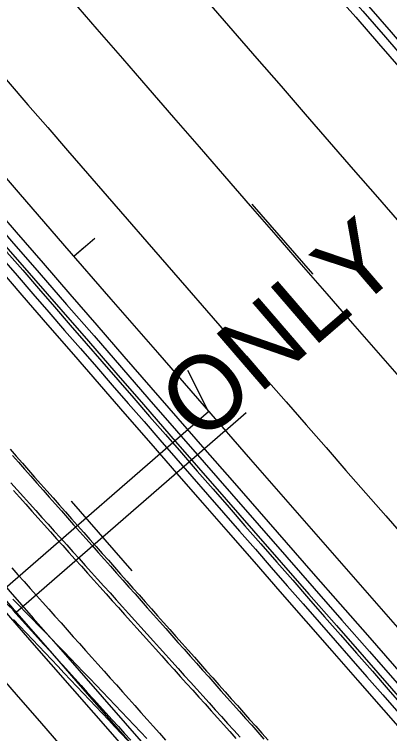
# Model space of a CAD drawing. Extents: x 2252205 to 2259955, y 13788514 to 13798103.
# Drawn here: x 2256454 to 2256494.6, y 13792111.5 to 13792189.4 of the extents above; entities that cross this region are included whole.
import ezdxf

# ---------------------------------------------------------------- set-up
doc = ezdxf.new("R2010")
doc.units = 0
for name, color, linetype in [('D_RDWY_TRACK_BUS', 7, 'Continuous'), ('D_RDWY_TRACK_TRUCK_KLEIN_CITY', 7, 'Continuous'), ('D_RDWY_TRACK_TRUCK_WB62', 7, 'Continuous'), ('GEOM_CENTERLINE_ALIGN', 7, 'Continuous'), ('GEOM_CENTERLINE_STA_100', 7, 'Continuous'), ('GEOM_CENTERLINE_STA_50', 7, 'Continuous'), ('ROAD_BIKE_SHARED_USE', 7, 'Continuous'), ('Road_Curb_Back', 7, 'Continuous'), ('Road_Curb_Face', 7, 'Continuous'), ('Road_EdgeOfPavementInside', 7, 'Continuous'), ('Road_EdgeOfPavementOutside', 7, 'Continuous'), ('ROAD_ROW_EXIST', 7, 'Continuous'), ('ROAD_ROW_PROPOSED', 7, 'Continuous'), ('ROAD_SCRATCH_DRIVE_CL', 7, 'Continuous'), ('ROAD_SCRATCH_PROP_KLEIN_LANES', 7, 'Continuous'), ('Road_Sidewalk_Back', 7, 'Continuous'), ('TRAF_PAVMRK_W_4IN_BRK', 7, 'Continuous'), ('TRAF_PAVMRK_W_4IN_SLD', 7, 'Continuous'), ('TRAF_PAVMRK_W_8IN_SLD', 7, 'Continuous'), ('TRAF_PAVMRK_W_LT_TRN_ARROW_WORD', 7, 'Continuous'), ('TRAF_PAVMRK_Y_4IN_SLD', 7, 'Continuous')]:
    doc.layers.add(name, color=color, linetype=linetype)

msp = doc.modelspace()

# ---------------------------------------------------------------- linework, layer by layer
at = {"layer": 'D_RDWY_TRACK_BUS'}
for points in [[(2256453.888, 13792137.831), (2256454.557, 13792137.083), (2256455.225, 13792136.335), (2256455.893, 13792135.587), (2256456.562, 13792134.839), (2256457.23, 13792134.091), (2256457.899, 13792133.344), (2256458.568, 13792132.597), (2256459.236, 13792131.85), (2256459.905, 13792131.103), (2256460.573, 13792130.356), (2256461.242, 13792129.61), (2256461.911, 13792128.863), (2256462.58, 13792128.117), (2256463.248, 13792127.371), (2256463.917, 13792126.624), (2256464.586, 13792125.879), (2256465.255, 13792125.133), (2256465.924, 13792124.387), (2256466.593, 13792123.641), (2256467.261, 13792122.896), (2256467.93, 13792122.15), (2256468.599, 13792121.405), (2256469.268, 13792120.66), (2256469.937, 13792119.915), (2256470.606, 13792119.17), (2256471.275, 13792118.425), (2256471.944, 13792117.68), (2256472.613, 13792116.935), (2256473.283, 13792116.19), (2256473.952, 13792115.446), (2256474.621, 13792114.701), (2256475.29, 13792113.957), (2256475.959, 13792113.212), (2256476.628, 13792112.468), (2256477.297, 13792111.723), (2256477.966, 13792110.979)], [(2256453.83, 13792124.845), (2256454.503, 13792124.106), (2256455.175, 13792123.366), (2256455.847, 13792122.626), (2256456.518, 13792121.887), (2256457.19, 13792121.147), (2256457.862, 13792120.407), (2256458.534, 13792119.666), (2256459.205, 13792118.926), (2256459.877, 13792118.186), (2256460.548, 13792117.445), (2256461.219, 13792116.705), (2256461.89, 13792115.964), (2256462.562, 13792115.223), (2256463.233, 13792114.483), (2256463.904, 13792113.742), (2256464.575, 13792113.001), (2256465.246, 13792112.26), (2256465.917, 13792111.519), (2256466.588, 13792110.778)]]:
    msp.add_lwpolyline(points, dxfattribs=at)
at = {"layer": 'D_RDWY_TRACK_TRUCK_KLEIN_CITY'}
for points in [[(2256453.533, 13792142.284), (2256454.197, 13792141.531), (2256454.861, 13792140.779), (2256455.526, 13792140.026), (2256456.19, 13792139.274), (2256456.854, 13792138.522), (2256457.519, 13792137.77), (2256458.183, 13792137.018), (2256458.847, 13792136.267), (2256459.512, 13792135.516), (2256460.176, 13792134.765), (2256460.841, 13792134.014), (2256461.505, 13792133.263), (2256462.169, 13792132.512), (2256462.834, 13792131.762), (2256463.498, 13792131.012), (2256464.162, 13792130.262), (2256464.827, 13792129.511), (2256465.491, 13792128.762), (2256466.155, 13792128.012), (2256466.82, 13792127.262), (2256467.484, 13792126.512), (2256468.149, 13792125.763), (2256468.813, 13792125.014), (2256469.477, 13792124.264), (2256470.142, 13792123.515), (2256470.806, 13792122.766), (2256471.47, 13792122.017), (2256472.135, 13792121.268), (2256472.799, 13792120.519), (2256473.463, 13792119.77), (2256474.128, 13792119.021), (2256474.792, 13792118.273), (2256475.457, 13792117.524), (2256476.121, 13792116.775), (2256476.785, 13792116.027), (2256477.45, 13792115.278), (2256478.114, 13792114.53), (2256478.779, 13792113.782), (2256479.443, 13792113.033), (2256480.107, 13792112.285), (2256480.772, 13792111.537), (2256481.436, 13792110.789)], [(2256453.781, 13792141.626), (2256454.444, 13792140.874), (2256455.107, 13792140.122), (2256455.77, 13792139.37), (2256456.433, 13792138.618), (2256457.096, 13792137.867), (2256457.759, 13792137.116), (2256458.422, 13792136.365), (2256459.086, 13792135.614), (2256459.749, 13792134.863), (2256460.412, 13792134.113), (2256461.076, 13792133.362), (2256461.739, 13792132.612), (2256462.403, 13792131.862), (2256463.066, 13792131.112), (2256463.73, 13792130.362), (2256464.394, 13792129.613), (2256465.057, 13792128.863), (2256465.721, 13792128.113), (2256466.385, 13792127.364), (2256467.048, 13792126.615), (2256467.712, 13792125.866), (2256468.376, 13792125.117), (2256469.04, 13792124.368), (2256469.704, 13792123.619), (2256470.368, 13792122.87), (2256471.032, 13792122.121), (2256471.696, 13792121.372), (2256472.36, 13792120.624), (2256473.024, 13792119.875), (2256473.688, 13792119.126), (2256474.352, 13792118.378), (2256475.016, 13792117.63), (2256475.68, 13792116.881), (2256476.344, 13792116.133), (2256477.008, 13792115.385), (2256477.672, 13792114.636), (2256478.336, 13792113.888), (2256479, 13792113.14), (2256479.665, 13792112.392), (2256480.329, 13792111.644), (2256480.993, 13792110.896)], [(2256453.722, 13792129.448), (2256454.388, 13792128.702), (2256455.053, 13792127.956), (2256455.719, 13792127.211), (2256456.384, 13792126.465), (2256457.05, 13792125.719), (2256457.715, 13792124.973), (2256458.381, 13792124.227), (2256459.046, 13792123.481), (2256459.711, 13792122.734), (2256460.376, 13792121.988), (2256461.042, 13792121.242), (2256461.707, 13792120.495), (2256462.372, 13792119.749), (2256463.037, 13792119.003), (2256463.702, 13792118.256), (2256464.367, 13792117.51), (2256465.032, 13792116.763), (2256465.697, 13792116.016), (2256466.362, 13792115.27), (2256467.027, 13792114.523), (2256467.692, 13792113.776), (2256468.357, 13792113.029), (2256469.022, 13792112.283), (2256469.686, 13792111.536), (2256470.351, 13792110.789)], [(2256453.845, 13792126.042), (2256454.54, 13792125.332), (2256455.234, 13792124.621), (2256455.928, 13792123.909), (2256456.622, 13792123.196), (2256457.314, 13792122.482), (2256458.006, 13792121.768), (2256458.697, 13792121.052), (2256459.388, 13792120.336), (2256460.078, 13792119.619), (2256460.768, 13792118.901), (2256461.456, 13792118.183), (2256462.145, 13792117.464), (2256462.832, 13792116.744), (2256463.52, 13792116.023), (2256464.206, 13792115.302), (2256464.893, 13792114.58), (2256465.578, 13792113.858), (2256466.263, 13792113.134), (2256466.948, 13792112.411), (2256467.632, 13792111.686), (2256468.316, 13792110.961)]]:
    msp.add_lwpolyline(points, dxfattribs=at)
at = {"layer": 'D_RDWY_TRACK_TRUCK_WB62'}
for points in [[(2256453.632, 13792138.634), (2256454.301, 13792137.89), (2256454.971, 13792137.145), (2256455.64, 13792136.4), (2256456.309, 13792135.656), (2256456.979, 13792134.911), (2256457.648, 13792134.167), (2256458.318, 13792133.422), (2256458.987, 13792132.678), (2256459.657, 13792131.934), (2256460.326, 13792131.19), (2256460.996, 13792130.446), (2256461.665, 13792129.702), (2256462.335, 13792128.958), (2256463.004, 13792128.214), (2256463.674, 13792127.47), (2256464.343, 13792126.726), (2256465.012, 13792125.982), (2256465.682, 13792125.239), (2256466.351, 13792124.495), (2256467.021, 13792123.751), (2256467.69, 13792123.008), (2256468.36, 13792122.264), (2256469.029, 13792121.52), (2256469.699, 13792120.777), (2256470.368, 13792120.033), (2256471.038, 13792119.29), (2256471.707, 13792118.547), (2256472.377, 13792117.803), (2256473.046, 13792117.06), (2256473.716, 13792116.316), (2256474.385, 13792115.573), (2256475.055, 13792114.83), (2256475.724, 13792114.087), (2256476.394, 13792113.343), (2256477.063, 13792112.6), (2256477.732, 13792111.857), (2256478.402, 13792111.114)], [(2256453.902, 13792123.837), (2256454.59, 13792123.116), (2256455.278, 13792122.395), (2256455.965, 13792121.673), (2256456.652, 13792120.95), (2256457.338, 13792120.227), (2256458.024, 13792119.504), (2256458.71, 13792118.78), (2256459.395, 13792118.055), (2256460.08, 13792117.331), (2256460.765, 13792116.605), (2256461.449, 13792115.88), (2256462.133, 13792115.153), (2256462.816, 13792114.427), (2256463.5, 13792113.7), (2256464.182, 13792112.973), (2256464.865, 13792112.245), (2256465.547, 13792111.517), (2256466.229, 13792110.788)]]:
    msp.add_lwpolyline(points, dxfattribs=at)
at = {"layer": 'GEOM_CENTERLINE_ALIGN'}
msp.add_arc((2265118.999, 13799669.27), 11459.16, 219.4185534, 224.3273853, dxfattribs=at)
at = {"layer": 'GEOM_CENTERLINE_STA_100'}
msp.add_line((2256460.417, 13792163.185), (2256462.684, 13792165.15), dxfattribs=at)
at = {"layer": 'GEOM_CENTERLINE_STA_50'}
msp.add_line((2256460.417, 13792163.185), (2256461.55, 13792164.167), dxfattribs=at)
at = {"layer": 'ROAD_BIKE_SHARED_USE'}
for radius, start, end in [(11494.993, 220.9250736, 223.155573), (11504.993, 220.9281736, 223.1564697)]:
    msp.add_arc((2265118.999, 13799669.27), radius, start, end, dxfattribs=at)
at = {"layer": 'Road_Curb_Back'}
for radius, start, end in [(11417.327, 220.7168327, 221.9218682), (11464.327, 220.6217644, 222.2961287), (11463.993, 220.6217644, 222.072794), (11489.993, 220.9232633, 223.1551241)]:
    msp.add_arc((2265118.999, 13799669.27), radius, start, end, dxfattribs=at)
at = {"layer": 'Road_Curb_Face'}
for radius, start, end in [(11418.16, 220.7168327, 221.9218682), (11489.16, 220.9232633, 223.1550492)]:
    msp.add_arc((2265118.999, 13799669.27), radius, start, end, dxfattribs=at)
at = {"layer": 'Road_EdgeOfPavementInside'}
for radius, end in [(11463.16, 222.0719881), (11465.16, 222.2969334)]:
    msp.add_arc((2265118.999, 13799669.27), radius, 220.6217644, end, dxfattribs=at)
at = {"layer": 'Road_EdgeOfPavementOutside'}
for radius, start, end in [(11418.16, 220.7168327, 221.9218682), (11489.16, 220.9232633, 223.1550492)]:
    msp.add_arc((2265118.999, 13799669.27), radius, start, end, dxfattribs=at)
at = {"layer": 'ROAD_ROW_EXIST'}
msp.add_arc((2265124.02, 13799672.913), 11509.2, 220.7607024, 223.0233974, dxfattribs=at)
at = {"layer": 'ROAD_ROW_PROPOSED'}
msp.add_arc((2265116.027, 13799666.586), 11519.16, 220.6777899, 223.1584667, dxfattribs=at)
at = {"layer": 'ROAD_SCRATCH_DRIVE_CL'}
for p, q in [((2256475.004, 13792146.391), (2256472.769, 13792150.799)), ((2256418.189, 13792096.945), (2256475.004, 13792146.391))]:
    msp.add_line(p, q, dxfattribs=at)
at = {"layer": 'ROAD_SCRATCH_PROP_KLEIN_LANES'}
for p, q in [((2256454.189, 13792124.613), (2256409.518, 13792164.768)), ((2256476.793, 13792144.294), (2256479.06, 13792146.26)), ((2256476.793, 13792144.294), (2256454.189, 13792124.613))]:
    msp.add_line(p, q, dxfattribs=at)
at = {"layer": 'Road_Sidewalk_Back'}
msp.add_arc((2265118.999, 13799669.27), 11411.327, 220.7168327, 221.9236801, dxfattribs=at)
at = {"layer": 'TRAF_PAVMRK_W_4IN_BRK'}
for points in [[(2256486.289, 13792161.27), (2256479.722, 13792168.812)], [(2256486.296, 13792161.263), (2256486.289, 13792161.27)], [(2256460.127, 13792136.659), (2256460.134, 13792136.652)], [(2256460.134, 13792136.652), (2256466.708, 13792129.116)]]:
    msp.add_lwpolyline(points, dxfattribs=at)
msp.add_arc((2265118.999, 13799669.27), 11441.16, 220.6468312, 223.3512093, dxfattribs=at)
at = {"layer": 'TRAF_PAVMRK_W_4IN_SLD'}
for radius, start, end in [(11419.16, 220.7168327, 221.9218682), (11488.16, 220.9232633, 223.3354344)]:
    msp.add_arc((2265118.999, 13799669.27), radius, start, end, dxfattribs=at)
at = {"layer": 'TRAF_PAVMRK_W_8IN_SLD'}
for radius, start, end in [(11430.16, 220.6468601, 221.9218682), (11452.16, 220.6468024, 221.6963939)]:
    msp.add_arc((2265118.999, 13799669.27), radius, start, end, dxfattribs=at)
at = {"layer": 'TRAF_PAVMRK_Y_4IN_SLD'}
for radius, start, end in [(11466.16, 220.621747, 223.3428022), (11462.16, 220.6467762, 222.0710209)]:
    msp.add_arc((2265118.999, 13799669.27), radius, start, end, dxfattribs=at)

# ---------------------------------------------------------------- texts
at = {"layer": 'TRAF_PAVMRK_W_LT_TRN_ARROW_WORD'}
msp.add_text('ONLY', height=8, rotation=40.70875, dxfattribs=at).set_placement((2256474.13, 13792142.751))

doc.saveas('drawing.dxf')
